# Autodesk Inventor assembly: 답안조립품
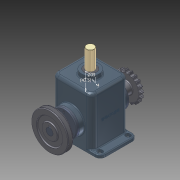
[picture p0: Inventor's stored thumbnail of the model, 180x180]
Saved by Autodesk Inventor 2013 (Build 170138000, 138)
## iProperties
Created: 2015-03
Part Number: 답안조립품
Document SubType Name: Assembly
Designer: Administrator
Mass: 8579.12 g
Surface Area: 4386.42 cm^2
Volume: 1982.52 cm^3
Density: 4.32738 g/cm^3
Author: Administrator
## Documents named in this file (15)
- C:\Documents and Settings\Administrator\바탕 화면\350305V1016\답안조립품.iam
- C:\Documents and Settings\Administrator\바탕 화면\350305V1016\본체.ipt
- C:\Documents and Settings\Administrator\바탕 화면\350305V1016\커버.ipt
- C:\Documents and Settings\Administrator\바탕 화면\350305V1016\오일실.ipt
- C:\Documents and Settings\Administrator\바탕 화면\350305V1016\베어링 6205.ipt
- C:\Documents and Settings\Administrator\바탕 화면\350305V1016\편심축.ipt
- C:\Documents and Settings\Administrator\바탕 화면\350305V1016\부시.ipt
- C:\Documents and Settings\Administrator\바탕 화면\350305V1016\멈춤링.ipt
- C:\Documents and Settings\Administrator\바탕 화면\350305V1016\키 8x8.ipt
- C:\Documents and Settings\Administrator\바탕 화면\350305V1016\슬라이드.ipt
- C:\Documents and Settings\Administrator\바탕 화면\350305V1016\체인 스프로킷.ipt
- C:\Documents and Settings\Administrator\바탕 화면\350305V1016\V-벨트풀리.ipt
- C:\Documents and Settings\Administrator\바탕 화면\350305V1016\멈춤나사 M5x0.5.ipt
- C:\Documents and Settings\Administrator\바탕 화면\350305V1016\M4x0.5.ipt
- C:\Documents and Settings\Administrator\바탕 화면\350305V1016\7-가변스프링.ipt
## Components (9 placed, 4 different names)
1. 5-체인 스프로킷:1 — 각도:4, 플러쉬:2
2. V-벨트풀리:1 — 각도:3, 플러쉬:1
3. 7-가변스프링:1
4. M4x0.5:1
5. M4x0.5:3
6. M4x0.5:4
7. M4x0.5:2
8. M4x0.5:5
9. M4x0.5:6
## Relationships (4: Angle 2, Flush 2)
- 각도:3 [Angle]: V-벨트풀리:1
- 플러쉬:1 [Flush]: V-벨트풀리:1
- 각도:4 [Angle]: 5-체인 스프로킷:1
- 플러쉬:2 [Flush]: 5-체인 스프로킷:1
